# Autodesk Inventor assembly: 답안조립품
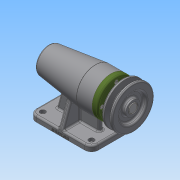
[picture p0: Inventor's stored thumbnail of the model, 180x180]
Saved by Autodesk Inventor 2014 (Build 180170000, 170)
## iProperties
Created: 2018-09
Part Number: 답안조립품
Document SubType Name: Assembly
Designer: net
Author: net
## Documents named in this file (12)
- C:\Users\net\Desktop\480907V1022\답안조립품.iam
- C:\Users\net\Desktop\480907V1022\답안분해도.ipt
- C:\Users\net\Desktop\480907V1022\축.ipt
- C:\Users\net\Desktop\480907V1022\키 5 x 5 x 16.ipt
- C:\Users\net\Desktop\480907V1022\베어링 6004.ipt
- C:\Users\net\Desktop\480907V1022\어댑터슬리브.ipt
- C:\Users\net\Desktop\480907V1022\볼트 M4.ipt
- C:\Users\net\Desktop\480907V1022\베어링 51202.ipt
- C:\Users\net\Desktop\480907V1022\커버.ipt
- C:\Users\net\Desktop\480907V1022\오일 실.ipt
- C:\Users\net\Desktop\480907V1022\V벨트풀리.ipt
- C:\Users\net\Desktop\480907V1022\멈춤나사 M3.ipt
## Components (1 placed, 1 different names)
1. V벨트풀리:1
